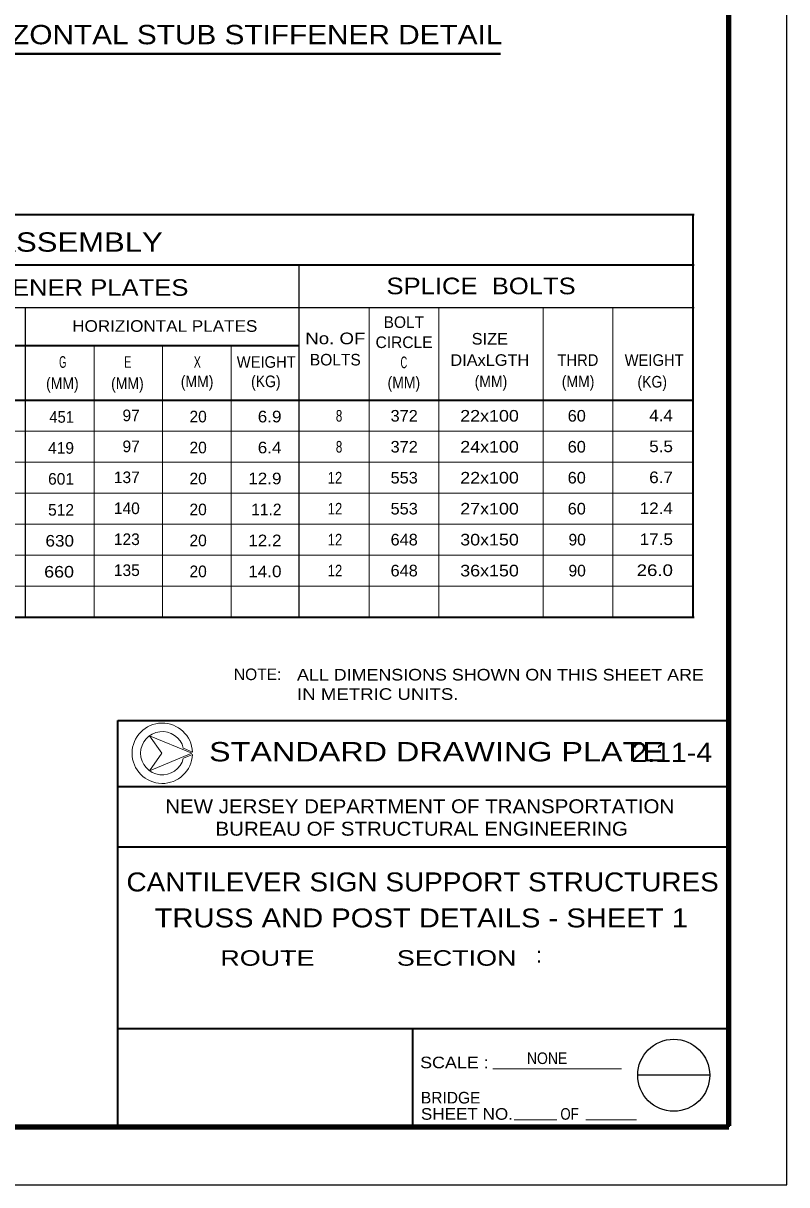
# Model space of a CAD drawing. Extents: x 312601.858 to 312602.699, y 144420.109 to 144420.704.
# Drawn here: x 312602.5016 to 312602.6988, y 144420.1095 to 144420.4096 of the extents above; entities that cross this region are included whole.
import ezdxf
from ezdxf.enums import TextEntityAlignment as Align

# ---------------------------------------------------------------- set-up
doc = ezdxf.new("R2010")
doc.units = 0
doc.header["$LTSCALE"] = 0.0012
for name, color, linetype, lineweight in [('1', 7, 'Continuous', 13), ('2', 7, 'Continuous', 25), ('39', 7, 'Continuous', 13)]:
    doc.layers.add(name, color=color, linetype=linetype, lineweight=lineweight)
doc.layers.add('4', color=7, linetype='Continuous')

msp = doc.modelspace()

# ---------------------------------------------------------------- linework, layer by layer
at = {"layer": '1', "lineweight": 40}
msp.add_line((312602.4799, 144420.4017), (312602.6249, 144420.4017), dxfattribs=at)
at = {"layer": '1', "lineweight": 35}
for p, q in [((312602.2321, 144420.3602), (312602.6749, 144420.3602)), ((312602.6746, 144420.256), (312602.6746, 144420.36)), ((312602.2321, 144420.3472), (312602.6749, 144420.3472)), ((312602.4314, 144420.3264), (312602.5729, 144420.3264)), ((312602.2321, 144420.3122), (312602.6746, 144420.3122)), ((312602.2321, 144420.2562), (312602.6749, 144420.2562))]:
    msp.add_line(p, q, dxfattribs=at)
at = {"layer": '1', "lineweight": 25}
for p, q in [((312602.5729, 144420.2562), (312602.5729, 144420.3472)), ((312602.2681, 144420.3362), (312602.6749, 144420.3362)), ((312602.5022, 144420.2562), (312602.5022, 144420.3362))]:
    msp.add_line(p, q, dxfattribs=at)
at = {"layer": '1'}
for p, q in [((312602.5909, 144420.2562), (312602.5909, 144420.3362)), ((312602.6089, 144420.2562), (312602.6089, 144420.3362)), ((312602.6359, 144420.2562), (312602.6359, 144420.3362)), ((312602.6539, 144420.2562), (312602.6539, 144420.3362)), ((312602.5199, 144420.2562), (312602.5199, 144420.3264)), ((312602.5376, 144420.2562), (312602.5376, 144420.3264)), ((312602.5553, 144420.2562), (312602.5553, 144420.3264)), ((312602.2332, 144420.3042), (312602.6746, 144420.3042)), ((312602.2321, 144420.2962), (312602.6746, 144420.2962)), ((312602.2321, 144420.2882), (312602.6746, 144420.2882)), ((312602.2321, 144420.2802), (312602.6746, 144420.2802)), ((312602.2321, 144420.2722), (312602.6746, 144420.2722)), ((312602.2321, 144420.2642), (312602.6746, 144420.2642)), ((312602.543, 144420.2197), (312602.5453, 144420.2207))]:
    msp.add_line(p, q, dxfattribs=at)
for points in [[(312602.5451, 144420.221), (312602.5342, 144420.2255), (312602.5451, 144420.221)], [(312602.5453, 144420.2213), (312602.543, 144420.2223), (312602.5429, 144420.2223)]]:
    msp.add_lwpolyline(points, dxfattribs=at)
for points in [[(312602.5451, 144420.221), (312602.5342, 144420.2255), (312602.5374, 144420.221), (312602.5342, 144420.2165)], [(312602.5374, 144420.221), (312602.5342, 144420.2165), (312602.5451, 144420.221), (312602.5342, 144420.2255)]]:
    msp.add_lwpolyline(points, close=True, dxfattribs=at)
for radius, start, end in [(0.0078026, 2.21392, 357.78608), (0.0056, 13.69411, 346.30589)]:
    msp.add_arc((312602.5375, 144420.221), radius, start, end, dxfattribs=at)
at = {"layer": '39', "lineweight": 25}
for p, q in [((312602.6988, 144420.1095), (312602.6988, 144420.7035)), ((312602.6789, 144420.1378), (312602.6603, 144420.1378)), ((312602.452, 144420.1245), (312602.6838, 144420.1245)), ((312601.8578, 144420.1095), (312602.6988, 144420.1095))]:
    msp.add_line(p, q, dxfattribs=at)
at = {"layer": '39', "lineweight": 158}
for p, q in [((312602.6838, 144420.1247), (312602.6838, 144420.6645)), ((312601.9088, 144420.1245), (312602.6838, 144420.1245))]:
    msp.add_line(p, q, dxfattribs=at)
at = {"layer": '39', "lineweight": 35}
for p, q in [((312602.526, 144420.1245), (312602.526, 144420.2295)), ((312602.526, 144420.2295), (312602.6838, 144420.2295)), ((312602.6838, 144420.2295), (312602.6838, 144420.1245)), ((312602.526, 144420.2124), (312602.6838, 144420.2124)), ((312602.526, 144420.1968), (312602.6838, 144420.1968)), ((312602.526, 144420.1499), (312602.6838, 144420.1499)), ((312602.6022, 144420.1248), (312602.6022, 144420.1499))]:
    msp.add_line(p, q, dxfattribs=at)
at = {"layer": '39'}
for p, q in [((312602.6022, 144420.1499), (312602.6838, 144420.1499)), ((312602.6022, 144420.1248), (312602.6022, 144420.1499)), ((312602.6022, 144420.1248), (312602.6022, 144420.1499)), ((312602.6229, 144420.1395), (312602.6561, 144420.1395)), ((312602.6284, 144420.1263), (312602.6394, 144420.1263)), ((312602.6469, 144420.1263), (312602.66, 144420.1263))]:
    msp.add_line(p, q, dxfattribs=at)
msp.add_lwpolyline([(312602.5451, 144420.221), (312602.5342, 144420.2255), (312602.5374, 144420.221), (312602.5342, 144420.2165)], close=True, dxfattribs=at)
at = {"layer": '39', "lineweight": 25}
msp.add_circle((312602.6696, 144420.1378), 0.0093005, dxfattribs=at)

# ---------------------------------------------------------------- texts
at = {"layer": '2'}
for s, height, width, p in [('HORIZONTAL STUB STIFFENER DETAIL', 0.005, 1.15, (312602.5523, 144420.4042)), ('STEEL  TRUSS  CHORD  SPLICE  ASSEMBLY', 0.005, 1.2, (312602.4518, 144420.3506)), ('STUB STIFFENER PLATES', 0.0043, 1.15, (312602.50255, 144420.3392)), ('SPLICE  BOLTS', 0.0043, 1.15, (312602.61985, 144420.3396)), ('HORIZIONTAL PLATES', 0.003, 1.1, (312602.53815, 144420.3299)), ('No. OF', 0.003, 1.2, (312602.5822, 144420.3267)), ('SIZE', 0.003, 1.05, (312602.6221, 144420.3266)), ('G', 0.003, 0.6, (312602.5118, 144420.3206)), ('E', 0.003, 0.7, (312602.5286, 144420.3206)), ('X', 0.003, 0.7, (312602.54655, 144420.3206)), ('WEIGHT', 0.003, 0.95, (312602.56435, 144420.3206)), ('C', 0.003, 0.6, (312602.5999, 144420.3205)), ('DIAxLGTH', 0.003, 1.05, (312602.6221, 144420.3211)), ('THRD', 0.003, 0.95, (312602.64485, 144420.3211)), ('WEIGHT', 0.003, 0.95, (312602.66455, 144420.3211)), ('(MM)', 0.003, 0.9, (312602.5117, 144420.3151)), ('(MM)', 0.003, 0.9, (312602.5285, 144420.3151)), ('(MM)', 0.003, 0.9, (312602.5465, 144420.3156)), ('(KG)', 0.003, 0.9, (312602.56425, 144420.3156)), ('(MM)', 0.003, 0.9, (312602.5999, 144420.3153)), ('(MM)', 0.003, 0.9, (312602.6224, 144420.3156)), ('(MM)', 0.003, 0.9, (312602.6449, 144420.3156)), ('(KG)', 0.003, 0.9, (312602.66405, 144420.3155)), ('2.11-4', 0.005, 1.1, (312602.6691, 144420.2187)), ('CANTILEVER SIGN SUPPORT STRUCTURES', 0.0049, 1.1, (312602.60475, 144420.1853)), ('TRUSS AND POST DETAILS - SHEET 1', 0.0049, 1.15, (312602.6044, 144420.176)), ('NONE', 0.003, 0.9, (312602.6369, 144420.1407))]:
    msp.add_text(s, height=height, dxfattribs=dict(at, width=width)).set_placement(p, align=Align.CENTER)
for s, p in [('BOLT', (312602.5999, 144420.3309)), ('CIRCLE', (312602.59995, 144420.3257)), ('BOLTS', (312602.5822, 144420.3212))]:
    msp.add_text(s, height=0.003, dxfattribs=at).set_placement(p, align=Align.CENTER)
for s, width, p in [('451', 0.95, (312602.5147, 144420.3064)), ('6.9', 1.1, (312602.5683, 144420.3065)), ('8', 0.75, (312602.584, 144420.3067)), ('372', 1.05, (312602.6035, 144420.3067)), ('22x100', 1.15, (312602.6296, 144420.3067)), ('60', 1.05, (312602.6469, 144420.3067)), ('4.4', 1.1, (312602.6694, 144420.3068)), ('6.4', 1.1, (312602.5683, 144420.2985)), ('8', 0.75, (312602.584, 144420.2987)), ('372', 1.05, (312602.6035, 144420.2987)), ('24x100', 1.15, (312602.6296, 144420.2987)), ('60', 1.05, (312602.6469, 144420.2987)), ('5.5', 1.1, (312602.6694, 144420.2988)), ('12.9', 1.1, (312602.5683, 144420.2905)), ('12', 0.85, (312602.584, 144420.2907)), ('553', 1.05, (312602.6035, 144420.2907)), ('22x100', 1.15, (312602.6296, 144420.2907)), ('60', 1.05, (312602.6469, 144420.2907)), ('6.7', 1.1, (312602.6694, 144420.2908)), ('12', 0.85, (312602.584, 144420.2827)), ('553', 1.05, (312602.6035, 144420.2827)), ('27x100', 1.15, (312602.6296, 144420.2827)), ('60', 1.05, (312602.6469, 144420.2827)), ('12.4', 1.1, (312602.6694, 144420.2828)), ('630', 1.1, (312602.5147, 144420.2744)), ('12.2', 1.1, (312602.5683, 144420.2745)), ('12', 0.85, (312602.584, 144420.2747)), ('648', 1.05, (312602.6035, 144420.2747)), ('30x150', 1.15, (312602.6296, 144420.2747)), ('17.5', 1.1, (312602.6694, 144420.2748)), ('660', 1.15, (312602.5147, 144420.2664)), ('14.0', 1.1, (312602.5683, 144420.2665)), ('12', 0.85, (312602.584, 144420.2667)), ('648', 1.05, (312602.6035, 144420.2667)), ('36x150', 1.15, (312602.6296, 144420.2667)), ('26.0', 1.2, (312602.6694, 144420.2668))]:
    msp.add_text(s, height=0.003, dxfattribs=dict(at, width=width)).set_placement(p, align=Align.RIGHT)
for s, p in [('97', (312602.5317, 144420.3068)), ('20', (312602.549, 144420.3065)), ('419', (312602.5147, 144420.2984)), ('97', (312602.5317, 144420.2988)), ('20', (312602.549, 144420.2985)), ('601', (312602.5147, 144420.2904)), ('137', (312602.5317, 144420.2908)), ('20', (312602.549, 144420.2905)), ('512', (312602.5147, 144420.2824)), ('140', (312602.5317, 144420.2828)), ('20', (312602.549, 144420.2825)), ('11.2', (312602.5683, 144420.2825)), ('123', (312602.5317, 144420.2748)), ('20', (312602.549, 144420.2745)), ('90', (312602.6469, 144420.2747)), ('135', (312602.5317, 144420.2668)), ('20', (312602.549, 144420.2665)), ('90', (312602.6469, 144420.2667))]:
    msp.add_text(s, height=0.003, dxfattribs=at).set_placement(p, align=Align.RIGHT)
at = {"layer": '39'}
for s, height, width, p in [('STANDARD DRAWING PLATE       ', 0.005, 1.25, (312602.61645, 144420.2189)), ('NEW JERSEY DEPARTMENT OF TRANSPORTATION', 0.003599, 1.1, (312602.604, 144420.2055)), ('BUREAU OF STRUCTURAL ENGINEERING', 0.0036, 1.1, (312602.6045, 144420.1997)), ('ROUTE           SECTION', 0.004, 1.3, (312602.59075, 144420.1661)), ('SCALE :', 0.003, 1.15, (312602.61295, 144420.1396)), ('OF', 0.003, 0.85, (312602.6427, 144420.1263))]:
    msp.add_text(s, height=height, dxfattribs=dict(at, width=width)).set_placement(p, align=Align.CENTER)
for p in [(312602.569737, 144420.1671), (312602.634837, 144420.1669)]:
    msp.add_text(':', height=0.004, dxfattribs=at).set_placement(p, align=Align.CENTER)
msp.add_text('BRIDGE', height=0.003, dxfattribs=at).set_placement((312602.6043, 144420.1305))
at = {"layer": '39', "width": 1.1}
msp.add_text('SHEET NO.', height=0.003, dxfattribs=at).set_placement((312602.6043, 144420.1263))
at = {"layer": '4'}
msp.add_text('NOTE:', height=0.003, dxfattribs=at).set_placement((312602.556, 144420.2399))
for s, width, p in [('ALL DIMENSIONS SHOWN ON THIS SHEET ARE', 1.15, (312602.5723, 144420.2398)), ('IN METRIC UNITS.', 1.2, (312602.5723, 144420.2348))]:
    msp.add_text(s, height=0.003, dxfattribs=dict(at, width=width)).set_placement(p)

doc.saveas('drawing.dxf')
